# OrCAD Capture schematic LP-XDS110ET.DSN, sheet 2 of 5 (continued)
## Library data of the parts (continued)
R33 = RESISTOR: RESISTOR, THICK FILM, 51k, -5%/+5%, 0.063W, 50V, -55DEGC/+155DEGC, 0402, SMD; Additional Datasheet URL: N/A; AutoDoc File: https://notefied-dynamic-precision.com/DB/Apps/Desktop/Item/Object.aspx?id=114564; BU Name: TEXAS INSTRUMENTS NORWAY; Budget Currency: EUR; Budget Price: 0.014; Budgetary Price: 0.014 EUR; Client Status: UNDER_REVIEW; Country of Origin: Israel; Datasheet URL: http://www.vishay.com/docs/20035/dcrcwe3.pdf; Datasheet URL 1: http://www.vishay.com/docs/20035/dcrcwe3.pdf; Datasheet URL 2: N/A; Definied Quality: INDUSTRIAL; Esd Level: N/A; Exclusive for Customers: TEXAS INSTRUMENTS NORWAY; Lead Time: 18; LifeCycle Status: ACTIVE; MPN: RESISTOR_0402_51k_+/-5%_50V_0.063W_M_+/-200ppm; MPN Status: ACTIVE; MSL: N/A; MTBF: N/A; MTBF Standard: N/A; Manufacturer: MANUFACTURER SELECTION; Mass: 0.00065g; Max Oper Temp: +155DEGC; Max TC: +200PPM/DEGC; Max Tol: +5%; Maximum Operating Temperature: +155DEGC; Maximum Temperature Coefficient: +200PPM/DEGC; Maximum Tolerance: +5%; Min Oper Temp: -55DEGC; Min TC: -200PPM/DEGC; Min Tol: -5%; Minimum Operating Temperature: -55DEGC; Minimum Temperature Coeficient: -200PPM/DEGC; Minimum Tolerance: -5%; Mounting Type: SMD; NOTE Status: PREFERRED; NOTEfied URL: https://notefied-dynamic-precision.com/NOTEfiedWebInterface/part/show?partNumber=01-22491; Notes: Standard item: Duplicate Reason: custom footprint for TEXAS INSTRUMENTS NORWAY.; Old Footprint: RESC1005X40N; PCB Package: 0402; Packing Size: 10000; Packing Type: Tape & Reel; Part Number: 01-22491; Part Type: Resistor|0402|STANDARD; REACH/SVHC Compliance: Compliant; REACH/SVHC Details: SVHC List Version Jun 20, 2016; REACH/SVHC Source: Material Declaration; REACH/SVHC Status: Unaffected; REACH/SVHC_COMPLIANCE: COMPLIANT; REACH/SVHC_DETAILS: SVHC LIST VERSION Jun 20, 2016; REACH/SVHC_SOURCE: MATERIAL DECLARATION; REACH/SVHC_STATUS: UNAFFECTED; ROHS: Exempt; Rated Current: N/A; Rated Power: 0.063W; Rated Voltage: 50V; Resistor Type: THICK FILM; Revision: R007; RoHS Status: ROHS_COMPLIANT; Rtd Current: N/A; Rtd Power: 0.063W; Rtd Voltage: 50V; Status: Released; Texas Part Status: Under Review; Type: Resistor; Vendor: VISHAY; Vendor Part Number: CRCW040251K0JNED; Vendor Part Status: Active; WEIGHT: 0.00065g
R34 = RESISTOR: RESISTOR, THICK FILM, 30k, -5%/+5%, 0.063W, 50V, -55DEGC/+155DEGC, 0402, SMD; Additional Datasheet URL: N/A; AutoDoc File: https://notefied-dynamic-precision.com/DB/Apps/Desktop/Item/Object.aspx?id=114563; BU Name: TEXAS INSTRUMENTS NORWAY; Budget Currency: EUR; Budget Price: 0.014; Budgetary Price: 0.014 EUR; Client Status: UNDER_REVIEW; Country of Origin: Missing Info; Datasheet URL: http://www.vishay.com/docs/20035/dcrcwe3.pdf; Datasheet URL 1: http://www.vishay.com/docs/20035/dcrcwe3.pdf; Datasheet URL 2: N/A; Definied Quality: INDUSTRIAL; Esd Level: N/A; Exclusive for Customers: TEXAS INSTRUMENTS NORWAY; Lead Time: 18; LifeCycle Status: ACTIVE; MPN: RESISTOR_0402_30k_+/-5%_50V_0.063W_M_+/-200ppm; MPN Status: ACTIVE; MSL: N/A; MTBF: N/A; MTBF Standard: N/A; Manufacturer: MANUFACTURER SELECTION; Mass: 0.00065g; Max Oper Temp: +155DEGC; Max TC: +200PPM/DEGC; Max Tol: +5%; Maximum Operating Temperature: +155DEGC; Maximum Temperature Coefficient: +200PPM/DEGC; Maximum Tolerance: +5%; Min Oper Temp: -55DEGC; Min TC: -200PPM/DEGC; Min Tol: -5%; Minimum Operating Temperature: -55DEGC; Minimum Temperature Coeficient: -200PPM/DEGC; Minimum Tolerance: -5%; Mounting Type: SMD; NOTE Status: PREFERRED; NOTEfied URL: https://notefied-dynamic-precision.com/NOTEfiedWebInterface/part/show?partNumber=01-22490; Notes: Standard item: Duplicate Reason: custom footprint for TEXAS INSTRUMENTS NORWAY.; Old Footprint: RESC1005X40N; PCB Package: 0402; Packing Size: 10000; Packing Type: Tape & Reel; Part Number: 01-22490; Part Type: Resistor|0402|STANDARD; REACH/SVHC Compliance: Compliant; REACH/SVHC Details: SVHC List Version Jun 20, 2016; REACH/SVHC Source: Material Declaration; REACH/SVHC Status: Unaffected; REACH/SVHC_COMPLIANCE: COMPLIANT; REACH/SVHC_DETAILS: SVHC LIST VERSION Jun 20, 2016; REACH/SVHC_SOURCE: MATERIAL DECLARATION; REACH/SVHC_STATUS: UNAFFECTED; ROHS: Exempt; Rated Current: N/A; Rated Power: 0.063W; Rated Voltage: 50V; Resistor Type: THICK FILM; Revision: R007; RoHS Status: ROHS_COMPLIANT; Rtd Current: N/A; Rtd Power: 0.063W; Rtd Voltage: 50V; Status: Released; Texas Part Status: Under Review; Type: Resistor; Vendor: VISHAY; Vendor Part Number: CRCW040230K0JNED; Vendor Part Status: Active; WEIGHT: 0.00065g
R84 = RESISTOR: RESISTOR, THICK FILM, 12k, -1%/+1%, 0.05W, 30V, -55DEGC/+155DEGC, 0201, SMD; ALT_SYMBOLS: RESC0603X35B2L,RESC0603X35B2M; Additional Datasheet URL: N/A; AutoDoc File: https://notefied-dynamic-precision.com/DB/Apps/Desktop/Item/Object.aspx?id=58894; BU Name: DYNAMIC PRECISION GDANSK; Budget Currency: USD; Budget Price: 0.0195; Budgetary Price: 0.0195 USD; Country of Origin: Taiwan; Datasheet URL: http://www.vishay.com/docs/20052/crcw0201e3.pdf; Datasheet URL 1: http://www.vishay.com/docs/20052/crcw0201e3.pdf; Datasheet URL 2: N/A; Lead Time: 7; Mass: 0.00017g; Max Oper Temp: +155DEGC; Max TC: +100PPM/DEGC; Max Tol: +1%; Maximum Operating Temperature: +155DEGC; Maximum Temperature Coefficient: +100PPM/DEGC; Maximum Tolerance: +1%; Min Oper Temp: -55DEGC; Min TC: -100PPM/DEGC; Min Tol: -1%; Minimum Operating Temperature: -55DEGC; Minimum Temperature Coeficient: -100PPM/DEGC; Minimum Tolerance: -1%; Mounting Type: SMD; NOTEfied URL: https://notefied-dynamic-precision.com/NOTEfiedWebInterface/part/show?partNumber=01-04087; PCB Package: 0201; Packing Size: 10000; Packing Type: Tape & Reel; Part Number: 01-04087; Part Type: Resistor|0201|PRECISION; REACH/SVHC Compliance: Compliant; REACH/SVHC Details: SVHC List Version Jan 12, 2017; REACH/SVHC Source: REACH Declaration; REACH/SVHC Status: Unaffected; ROHS: Exempt; Rated Current: N/A; Rated Power: 0.05W; Rated Voltage: 30V; Resistor Type: THICK FILM; Revision: R007; RoHS Status: ROHS_COMPLIANT; Rtd Current: N/A; Rtd Power: 0.05W; Rtd Voltage: 30V; Status: Released; Texas Part Status: Under Review; Type: Resistor; Vendor: VISHAY; Vendor Part Number: CRCW020112K0FKED; Vendor Part Status: Active; Weight: 0.00017g
R87 = RESISTOR: RESISTOR, THICK FILM, 1M, -1%/+1%, 0.063W, 50V, -55DEGC/+155DEGC, 0402, SMD; Additional Datasheet URL: N/A; AutoDoc File: https://notefied-dynamic-precision.com/DB/Apps/Desktop/Item/Object.aspx?id=114549; BU Name: TEXAS INSTRUMENTS NORWAY; Budget Currency: EUR; Budget Price: 0.012; Budgetary Price: 0.012 EUR; Client Status: UNDER_REVIEW; Country of Origin: Israel; Datasheet URL: http://www.vishay.com/docs/20035/dcrcwe3.pdf; Datasheet URL 1: http://www.vishay.com/docs/20035/dcrcwe3.pdf; Datasheet URL 2: N/A; Exclusive for Customers: TEXAS INSTRUMENTS NORWAY; Lead Time: 14; Mass: 0.00060916g; Max Oper Temp: +155DEGC; Max TC: +100PPM/DEGC; Max Tol: +1%; Maximum Operating Temperature: +155DEGC; Maximum Temperature Coefficient: +100PPM/DEGC; Maximum Tolerance: +1%; Min Oper Temp: -55DEGC; Min TC: -100PPM/DEGC; Min Tol: -1%; Minimum Operating Temperature: -55DEGC; Minimum Temperature Coeficient: -100PPM/DEGC; Minimum Tolerance: -1%; Mounting Type: SMD; NOTEfied URL: https://notefied-dynamic-precision.com/NOTEfiedWebInterface/part/show?partNumber=01-22476; Notes: Standard item: Duplicate Reason: custom footprint for TEXAS INSTRUMENTS NORWAY.; PCB Package: 0402; Packing Size: 10000; Packing Type: Tape & Reel; Part Number: 01-22476; Part Type: Resistor|0402|PRECISION; REACH/SVHC Compliance: Compliant; REACH/SVHC Details: SVHC List Version Jun 20, 2016; REACH/SVHC Source: Material Declaration; REACH/SVHC Status: Unaffected; ROHS: Exempt; Rated Current: N/A; Rated Power: 0.063W; Rated Voltage: 50V; Resistance: 1M; Resistor Type: THICK FILM; Revision: R011; RoHS Status: ROHS_COMPLIANT_WITH_EXEMPTION; Rtd Current: N/A; Rtd Power: 0.063W; Rtd Voltage: 50V; Status: Released; Texas Part Status: Under Review; Type: Resistor; Vendor: VISHAY; Vendor Part Number: CRCW04021M00FKED; Vendor Part Status: Active; Weight: 0.00060916g
R93 = RESISTOR: RESISTOR, THICK FILM, 20k, -5%/+5%, 0.05W, 30V, -55DEGC/+155DEGC, 0201, SMD; ALT_SYMBOLS: RESC0603X35B2L,RESC0603X35B2M; Additional Datasheet URL: N/A; AutoDoc File: https://notefied-dynamic-precision.com/DB/Apps/Desktop/Item/Object.aspx?id=59010; BU Name: DYNAMIC PRECISION GDANSK; Budget Currency: USD; Budget Price: 0.0041; Budgetary Price: 0.0041 USD; Country of Origin: Taiwan; Datasheet URL: http://www.vishay.com/docs/20052/crcw0201e3.pdf; Datasheet URL 1: http://www.vishay.com/docs/20052/crcw0201e3.pdf; Datasheet URL 2: N/A; Lead Time: 7; Mass: 0.00017g; Max Oper Temp: +155DEGC; Max TC: +200PPM/DEGC; Max Tol: +5%; Maximum Operating Temperature: +155DEGC; Maximum Temperature Coefficient: +200PPM/DEGC; Maximum Tolerance: +5%; Min Oper Temp: -55DEGC; Min TC: -200PPM/DEGC; Min Tol: -5%; Minimum Operating Temperature: -55DEGC; Minimum Temperature Coeficient: -200PPM/DEGC; Minimum Tolerance: -5%; Mounting Type: SMD; NOTEfied URL: https://notefied-dynamic-precision.com/NOTEfiedWebInterface/part/show?partNumber=01-04203; PCB Package: 0201; Packing Size: 10000; Packing Type: Tape & Reel; Part Number: 01-04203; Part Type: Resistor|0201|STANDARD; REACH/SVHC Compliance: Compliant; REACH/SVHC Details: SVHC List Version Jan 12, 2017; REACH/SVHC Source: REACH Declaration; REACH/SVHC Status: Unaffected; ROHS: Exempt; Rated Current: N/A; Rated Power: 0.05W; Rated Voltage: 30V; Resistor Type: THICK FILM; Revision: R007; RoHS Status: ROHS_COMPLIANT; Rtd Current: N/A; Rtd Power: 0.05W; Rtd Voltage: 30V; Status: Released; Texas Part Status: Under Review; Type: Resistor; Vendor: VISHAY; Vendor Part Number: CRCW020120K0JNED; Vendor Part Status: Active; Weight: 0.00017g
R353 = RESISTOR: RESISTOR, THICK FILM, 4.7k, -5%/+5%, 0.063W, 50V, -55DEGC/+155DEGC, 0402, SMD; Additional Datasheet URL: N/A; Budgetary Price: 0.014 EUR; Country of Origin: Israel; Datasheet URL: http://www.vishay.com/docs/20035/dcrcwe3.pdf; Exclusive for Customers: TEXAS INSTRUMENTS NORWAY; Lead Time: 18; Mass: 0.00065g; Maximum Operating Temperature: +155DEGC; Maximum Temperature Coefficient: +200PPM/DEGC; Maximum Tolerance: +5%; Minimum Operating Temperature: -55DEGC; Minimum Temperature Coeficient: -200PPM/DEGC; Minimum Tolerance: -5%; Mounting Type: SMD; NOTEfied URL: https://notefied-dynamic-precision.com/NOTEfiedWebInterface/part/show?partNumber=01-22489; Notes: Standard item: Duplicate Reason: custom footprint for TEXAS INSTRUMENTS NORWAY.; PCB Package: 0402; Packing Size: 10000; Packing Type: Tape & Reel; Part Number: 01-22489; Part Type: Resistor|0402|STANDARD; REACH/SVHC Compliance: Compliant; REACH/SVHC Details: SVHC List Version Jun 20, 2016; REACH/SVHC Source: Material Declaration; REACH/SVHC Status: Unaffected; ROHS: Exempt; Rated Current: N/A; Rated Power: 0.063W; Rated Voltage: 50V; Resistor Type: THICK FILM; Revision: R009; Status: Released; Texas Part Status: Under Review; Type: Resistor; Vendor: VISHAY; Vendor Part Number: CRCW04024K70JNED; Vendor Part Status: Active
R357 R358 = RESISTOR: RESISTOR, THICK FILM, 5.1k, -5%/+5%, 0.05W, 30V, -55DEGC/+155DEGC, 0201, SMD; ALT_SYMBOLS: RESC0603X35B2L,RESC0603X35B2M; Additional Datasheet URL: N/A; Budgetary Price: 0.005 EUR; Country of Origin: Taiwan; Datasheet URL: https://www.vishay.com/docs/20052/crcw0201e3.pdf; Lead Time: 20; Mass: 0.00017g; Maximum Operating Temperature: +155DEGC; Maximum Temperature Coefficient: +200PPM/DEGC; Maximum Tolerance: +5%; Minimum Operating Temperature: -55DEGC; Minimum Temperature Coeficient: -200PPM/DEGC; Minimum Tolerance: -5%; Mounting Type: SMD; NOTEfied URL: https://notefied-dynamic-precision.com/NOTEfiedWebInterface/part/show?partNumber=01-04189; PCB Package: 0201; Packing Size: 10000; Packing Type: Tape & Reel; Part Number: 01-04189; Part Type: Resistor|0201|STANDARD; ROHS: Exempt; Rated Current: N/A; Rated Power: 0.05W; Rated Voltage: 30V; Resistor Type: THICK FILM; Revision: R008; Status: Released; Type: Resistor; Vendor: VISHAY; Vendor Part Number: CRCW02015K10JNED; Vendor Part Status: Active
U5 = IC_PROC_MSP432E401Y_TQFP128: IC, MICROCONTROLLER, SIMPLELINK ETHERNET MICROCONTROLLER, 2.97V TO 3.63V, TQFP128, SMD; ALT_SYMBOLS: QFP40P1600X1600X120-128A2L,QFP40P1600X1600X120-128A2M; Additional Datasheet URL: http://www.ti.com/lit/ml/mpqf013/mpqf013.pdf; Budgetary Price: 9.31 USD; Country of Origin: Philippines; Datasheet URL: http://www.ti.com/lit/ds/symlink/msp432e401y.pdf; Frequency: 120MHz; Mass: 0.5774g; Maximum Operating Temperature: +105DEGC; Minimum Operating Temperature: -40DEGC; Mounting Type: SMD; NOTEfied URL: https://notefied-dynamic-precision.com/NOTEfiedWebInterface/part/show?partNumber=18-35458; PCB Package: TQFP128; Packing Size: 90; Packing Type: Tray; Part Number: 18-35458; Part Type: IC|MICROCONTROLLER|TEXAS INSTRUMENTS; REACH/SVHC Compliance: Compliant; REACH/SVHC Details: SVHC List Version Jan 15, 2019; REACH/SVHC Source: REACH Declaration; REACH/SVHC Status: Unaffected; ROHS: Compliant; Rated Voltage: 2.97V TO 3.63V; Revision: R002; Status: Released; Texas Part Status: Under Review; Type: IC; Vendor: TEXAS INSTRUMENTS; Vendor Part Status: Active
U6 = IC_REF_LM4040_SC70-5: IC, ANALOG, PRECISION MICROPOWER SHUNT VOLTAGE REFERENCE, 2.5V, SC70-5, SMD; ALT_SYMBOLS: SOT65P210X110-5L,SOT65P210X110-5M; Additional Datasheet URL: http://www.ti.com/litv/pdf/mpds025f; AutoDoc File: http://notefied-dynamic-precision.com/DB/Apps/Desktop/Item/Object.aspx?id=96645; Budget Currency: USD; Budget Price: 0.78; Budgetary Price: 0.71 USD; Country of Origin: Missing Info; Datasheet URL: http://www.ti.com/lit/ds/symlink/lm4040.pdf; Datasheet URL 1: http://www.ti.com/lit/ml/mpds025f/mpds025f.pdf; Datasheet URL 2: http://www.ti.com/lit/ds/symlink/lm4040b25.pdf; Definied Quality: INDUSTRIAL; Esd Level: N/A; FPLIST: SOT65P210X110-5N,SOT65P210X110-5L,SOT65P210X110-5M; Lead Time: 7; MPN: LM4040B25IDCKR; MPN Status: ACTIVE; MSL: 1; Manufacturer: TEXAS INSTRUMENTS; Mass: 0.0068g; Max Oper Temp: +85DEGC; Maximum Operating Temperature: +85DEGC; Min Oper Temp: -40DEGC; Minimum Operating Temperature: -40DEGC; Mounting Type: SMD; NOTE Status: PREFERRED; NOTEfied URL: https://notefied-dynamic-precision.com/NOTEfiedWebInterface/part/show?partNumber=18-29558; PCB Package: SC70-5; Packing Size: 3000; Packing Type: Tape & Reel; Part Number: 18-29558; Part Type: IC|ANALOG|PM|REFERENCE; REACH/SVHC Compliance: Compliant; REACH/SVHC Details: SVHC List Version Jun 20, 2016; REACH/SVHC Source: Material Declaration; REACH/SVHC Status: Unaffected; ROHS: Compliant; Rated Voltage: 2.5V; Revision: R006; RoHS Status: ROHS_COMPLIANT; Rtd Voltage: 2.5V; Status: Released; Texas Part Status: Under Review; Type: IC; Vendor: TEXAS INSTRUMENTS; Vendor Part Number: LM4040B25IDCKR; Vendor Part Status: Active; WEIGHT: 0.011098173g
U7 = IC_PM_TPS79601_SON8: IC, ANALOG, ULTRALOW-NOISE, HIGH PSRR, FAST, RF, 1A LOW-DROPOUT LINEAR REGULATORS, VIN:2.7V TO 5.5V, VOUT:1.2V TO 5.5V, SON8, SMD; ALT_SYMBOLS: SON65P300X300X100-9AL,SON65P300X300X100-9AM; Additional Datasheet URL: http://www.ti.com/litv/pdf/mpds118j; AutoDoc File: http://notefied-dynamic-precision.com/DB/Apps/Desktop/Item/Object.aspx?id=96546; Budget Currency: USD; Budget Price: 1; Budgetary Price: 1 USD; Country of Origin: Malaysia; Datasheet URL: http://www.ti.com/lit/ds/symlink/tps796.pdf; Datasheet URL 1: http://www.ti.com/litv/pdf/mpds118j; Datasheet URL 2: http://www.ti.com/lit/ds/symlink/tps79601.pdf; FPLIST: SON65P300X300X100-9AN,SON65P300X300X100-9AL,SON65P300X300X100-9AM; Lead Time: 6; LifeCycle Status: ACTIVE; MPN: TPS79601DRBR; MPN Status: ACTIVE; MSL: 2; Manufacturer: TEXAS INSTRUMENTS; Mass: 0.0247g; Max Oper Temp: +125DEGC; Maximum Operating Temperature: +125DEGC; Min Oper Temp: -40DEGC; Minimum Operating Temperature: -40DEGC; Mounting Type: SMD; NOTE Status: PREFERRED; NOTEfied URL: https://notefied-dynamic-precision.com/NOTEfiedWebInterface/part/show?partNumber=18-29530; PCB Package: SON8; Packing Size: 3000; Packing Type: Tape & Reel; Part Number: 18-29530; Part Type: IC|ANALOG|PM|REGULATOR; REACH/SVHC Compliance: Compliant; REACH/SVHC Details: SVHC List Version Jun 20, 2016; REACH/SVHC Source: Material Declaration; REACH/SVHC Status: Unaffected; ROHS: Compliant; Rated Voltage: 1.2V TO 5.4V; Revision: R006; RoHS Status: ROHS_COMPLIANT; Rtd Voltage: 1.2V TO 5.4V; Status: Released; Texas Part Status: Under Review; Type: IC; Vendor: TEXAS INSTRUMENTS; Vendor Part Number: TPS79601DRBR; Vendor Part Status: Active; WEIGHT: 0.024660813g
U15 = IC_PROC_USB3300_QFN32: IC, DIGITAL, INTERFACE, HI-SPEED USB HOST, 3.3V, QFN32-EP, SMD; ALT_SYMBOLS: QFNWB50P500X500X100-33L,QFNWB50P500X500X100-33M,QFNWB50P500X500X100-33DL,QFNWB50P500X500X100-33DM; Additional Datasheet URL: http://www.microchip.com/wwwproducts/Devices.aspx?product=USB3300#pricindAndSamples; AutoDoc File: https://notefied-dynamic-precision.com/DB/Apps/Desktop/Item/Object.aspx?id=73764; BU Name: DYNAMIC PRECISION GDANSK; Budget Currency: USD; Budget Price: 0.91; Budgetary Price: 0.91 USD; CLASS: IC; Client Status: UNDER_REVIEW; Country of Origin: China; Datasheet URL: http://ww1.microchip.com/downloads/en/DeviceDoc/00001783C.pdf; Datasheet URL 1: http://ww1.microchip.com/downloads/en/DeviceDoc/00001783B.pdf; Datasheet URL 2: http://www.microchip.com/wwwproducts/Devices.aspx?product=USB3300#pricindAndSamples; FPLIST: QFNWB50P500X500X100-33N,QFNWB50P500X500X100-33DN; Lead Time: 2; Mass: 0.0636g; Max Oper Temp: +85DEGC; Maximum Operating Temperature: +85DEGC; Min Oper Temp: -40DEGC; Minimum Operating Temperature: -40DEGC; Mounting Type: SMD; NOTEfied URL: https://notefied-dynamic-precision.com/NOTEfiedWebInterface/part/show?partNumber=18-26311; PCB Package: QFN32-EP; Packing Size: 4900; Packing Type: Tray; Part Number: 18-26311; Part Type: IC|DIGITAL|INTERFACE|USB; REACH/SVHC Compliance: Compliant; REACH/SVHC Details: SVHC List Version Jun 20, 2016; REACH/SVHC Source: Material Declaration; REACH/SVHC Status: Unaffected; ROHS: Compliant; Rated Voltage: 3.3V; Revision: R010; RoHS Status: ROHS_COMPLIANT; Rtd Voltage: 3.3V; Status: Released; Texas Part Status: Under Review; Type: IC; Vendor: MICROCHIP; Vendor Part Status: Active; Weight: 0.0636g
U47 = IC_PM_TPS259530_WSON8: IC, ANALOG, EFUSE WITH FAST OVERVOLTAGE PROTECTION, 2.7V TO 18V, WSON8-EP, SMD; ALT_SYMBOLS: SON50P200X200X80-9A2L,SON50P200X200X80-9A2M; Additional Datasheet URL: N/A; Budgetary Price: 0.4 USD; Datasheet URL: http://www.ti.com/lit/ds/symlink/tps2595.pdf; Mass: 0.0119g; Maximum Operating Temperature: +125DEGC; Minimum Operating Temperature: -40DEGC; Mounting Type: SMD; NOTEfied URL: https://notefied-dynamic-precision.com/NOTEfiedWebInterface/part/show?partNumber=18-34886; PCB Package: WSON8-EP; Packing Size: 3000; Packing Type: Tape & Reel; Part Number: 18-34886; Part Type: IC|ANALOG|PM|HOTSWAP; REACH/SVHC Details: SVHC List Version; ROHS: Compliant; Rated Current: 4A; Rated Voltage: 2.7V TO 18V; Revision: R001; Status: Released; Texas Part Status: Under Review; Type: IC; Vendor: TEXAS INSTRUMENTS; Vendor Part Number: TPS259530DSGR; Vendor Part Status: Active
Y3 = XTAL_4: CRYSTAL, RESONATOR, 16MHz, -30PPM/+30PPM, -40DEGC/+85DEGC, SMD; ALT_SYMBOLS: OSCCC250X320X100-4BL,OSCCC250X320X100-4BM; Additional Datasheet URL: http://www.ndk.com/en/products/search/crystal/1188120_1494.html; AutoDoc File: http://notefied-dynamic-precision.com/DB/Apps/Desktop/Item/Object.aspx?id=96470; Budgetary Price: 0.3881 USD; Capacitance: 8pF; Country of Origin: Missing Info; Datasheet URL: http://www.ndk.com/images/products/catalog/c_NX3225GA-STD-CRG-2_e.pdf; Datasheet URL 1: N/A; Datasheet URL 2: http://www.ndk.com/images/products/catalog/c_NX3225GA-STD-CRG-2_e.pdf; FPLIST: OSCCC250X320X100-4BN,OSCCC250X320X100-4BL,OSCCC250X320X100-4BM; MPN: NX3225GA-16.000M-STD-CRG-1; MPN Status: ACTIVE; Manufacturer: NIHON DEMPA KOGYO; Mass: N/A; Max Oper Temp: +85DEGC; Max TC: +30PPM/DEGC; Max Tol: +20PPM; Maximum Operating Temperature: +85DEGC; Maximum Stability: +30PPM; Maximum Tolerance: +20PPM; Min Oper Temp: -40DEGC; Min TC: -30PPM/DEGC; Min Tol: -20PPM; Minimum Operating Temperature: -40DEGC; Minimum Stability: -30PPM; Minimum Tolerance: -20PPM; Mounting Type: SMD; NOTE Status: PREFERRED; NOTEfied URL: https://notefied-dynamic-precision.com/NOTEfiedWebInterface/part/show?partNumber=12-00745; Packing Size: 3000; Packing Type: Tape & Reel; Part Number: 12-00745; Part Type: Crystal|RESONATOR; REACH/SVHC Compliance: Compliant; REACH/SVHC Details: SVHC List Version Jun 20, 2016; REACH/SVHC Source: REACH Declaration; REACH/SVHC Status: Unaffected; ROHS: Exempt; Rated Voltage: N/A; Revision: R009; RoHS Status: ROHS_COMPLIANT; Status: Released; Texas Part Status: Under Review; Type: Crystal; Vendor: NIHON DEMPA KOGYO; Vendor Part Number: NX3225GA-16.000M-STD-CRG-1; Vendor Part Status: Active
Y4 = XTAL_4: CRYSTAL, RESONATOR, 24MHz, -50PPM/+50PPM, -40DEGC/+85DEGC, SMD; ALT_SYMBOLS: OSCCC250X320X70-4AL,OSCCC250X320X70-4AM; Additional Datasheet URL: http://www5.epsondevice.com/en/products/crystal_unit/fa238.html; AutoDoc File: https://notefied-dynamic-precision.com/DB/Apps/Desktop/Item/Object.aspx?id=96049; BU Name: DYNAMIC PRECISION GDANSK; Budget Currency: N/A; Budget Price: N/A; Capacitance: 12pF; Client Status: UNDER_REVIEW; Country of Origin: Japan; Datasheet URL: https://support.epson.biz/td/api/doc_check.php?mode=dl&lang=en&Parts=FA-238; Datasheet URL 1: https://support.epson.biz/td/api/doc_check.php?mode=dl&lang=en&Parts=FA-238; Datasheet URL 2: http://www5.epsondevice.com/en/products/mhz_range/fa238.html; Mass: 0.016g; Max Oper Temp: +85DEGC; Max TC: +50PPM; Max Tol: +50PPM; Maximum Operating Temperature: +85DEGC; Maximum Stability: +50PPM; Maximum Tolerance: +50PPM; Min Oper Temp: -40DEGC; Min TC: -50PPM; Min Tol: -50PPM; Minimum Operating Temperature: -40DEGC; Minimum Stability: -50PPM; Minimum Tolerance: -50PPM; Mounting Type: SMD; NOTEfied URL: https://notefied-dynamic-precision.com/NOTEfiedWebInterface/part/show?partNumber=12-00730; Packing Size: 1000; Packing Type: Tape & Reel; Part Number: 12-00730; Part Type: Crystal|RESONATOR; REACH/SVHC Compliance: Compliant; REACH/SVHC Details: SVHC List Version Jan 12, 2017; REACH/SVHC Source: REACH Declaration; REACH/SVHC Status: Unaffected; ROHS: Compliant; Rated Voltage: N/A; Revision: R008; RoHS Status: ROHS_COMPLIANT; Rtd Voltage: N/A; Status: Released; Texas Part Status: Under Review; Type: Crystal; Vendor: EPSON; Vendor Part Number: FA-238 24.0000MB50X-W0; Vendor Part Status: Active; Weight: 0.016g

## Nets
5V0: C48.1 C110.1 C111.1 FL2.1 R92.2 U7.1(IN) U7.2(IN) U7.8(EN) ; also on sheet 1 4
GND: C1.2 C2.2 C3.2 C4.2 C6.2 C7.2 C8.2 C9.2 C38.2 C39.2 C40.2 C42.2 C43.2 C44.2 C45.2 C46.2 C48.2 C49.2 C50.2 C78.2 C79.2 C80.2 C83.2 C84.2 C85.2 C86.2 C87.2 C88.1 C89.2 C108.2 C109.2 C110.2 C111.2 C113.2 CR4.1(C) CR5.1(C) CR6.3 CR15.2(ANODE) J1.C1(GND) J1.C2(GND) J1.C15(GND) J1.C16(GND) J1.M1(SHIELD) J1.M2(SHIELD) J1.M3(SHIELD) J1.M4(SHIELD) P8.3(7) P8.5(8) P8.9(10) R28.1 R29.2 R30.2 R34.1 R84.1 R90.1 R91.1 R93.2 R353.1 R357.1 R358.1 U5.10(GNDA) U5.17(GND) U5.48(GND) U5.55(GND) U5.58(GND) U5.64(nWAKE) U5.66(XOSC0) U5.80(GND) U5.114(GND) U6.1(ANODE) U7.6(GND) U7.9(GND/TAB) U15.1(GND) U15.2(GND) U15.33(EGP) U47.8(GND) U47.9(EGP) Y3.2 Y3.4 Y4.2 Y4.4 ; also on sheet 1 3 4 5
VBUS_DET: R92.1 R93.1 U5.12(PE3/AIN0)
VDDC: C43.1 C44.1 C45.1 U5.87(VDDC) U5.115(VDDC)
ET_BYPASS: U5.78(PM0) ; also on sheet 3
ET_CAL0: U5.74(PM4) ; also on sheet 3
ET_CAL1: U5.73(PM5) ; also on sheet 3
ET_CAL2: U5.23(PC6/C0+) ; also on sheet 3
ET_CALIBRATE: U5.77(PM1) ; also on sheet 3
ET_PM2: U5.76(PM2) ; also on sheet 3
ET_PN3: U5.110(PN3) ; also on sheet 3
ET_SSICLK: U5.120(PB5/AIN11) ; also on sheet 3
ET_SSIDAT0: U5.123(PE4/AIN9) ; also on sheet 3
ET_SSIDAT1: U5.124(PE5/AIN8) ; also on sheet 3
ET_SSIFSS: U5.121(PB4/AIN10) ; also on sheet 3
IRSTn: P8.10(5) R20.2
ITCK: P8.4(2) U5.100(PC0/TCK/SWCLK)
ITDI: P8.8(4) U5.98(PC2/TDI)
ITDO: P8.6(3) U5.97(PC3/TDO/SWO)
ITMS: P8.2(1) U5.99(PC1/TMS/SWDIO)
USB1V8: C83.1 C84.1 C85.1 U15.15(VDD1.8) U15.26(VDD1.8)
USB_VBUS: CR6.6 J1.C3(VBUS) J1.C4(VBUS) J1.C13(VBUS) J1.C14(VBUS) R82.2 U47.2(EN/UVLO) U47.3(IN) U47.4(IN)
USBA1V8: C86.1 C87.1 U15.29(VDDA1.8)
USBCLK: U5.92(PB3/I2C0SDA) U15.14(CLKOUT)
USBD0: U5.81(PL0) U15.24(DATA0)
USBD1: U5.82(PL1) U15.23(DATA1)
USBD2: U5.83(PL2) U15.22(DATA2)
USBD3: U5.84(PL3) U15.21(DATA3)
USBD4: U5.85(PL4) U15.20(DATA4)
USBD5: U5.86(PL5) U15.19(DATA5)
USBD6: U5.106(PP5) U15.18(DATA6)
USBD7: U5.105(PP4) U15.17(DATA7)
USBDIR: U5.104(PP3) U15.12(DIR)
USBDM: CR6.4 J1.C7(DN1) J1.C10(DN2) U15.8(DM)
USBDP: CR6.5 J1.C6(DP1) J1.C11(DP2) U15.7(DP)
USBNXT: U5.103(PP2) U15.11(NXT)
USBSTP: U5.91(PB2/I2C0SCL) U15.13(STP)
XDS_BID_SCL: U5.112(PN5) ; also on sheet 1
XDS_BID_SDA: U5.111(PN4) ; also on sheet 1
XDS_DIR_GPIO1: U5.116(PJ0) ; also on sheet 1
XDS_DIR_GPIO2: U5.117(PJ1) ; also on sheet 1
XDS_GPIO1: U5.43(PF1) ; also on sheet 1
XDS_GPIO2: U5.44(PF2) ; also on sheet 1
XDS_GPIO3: U5.42(PF0) ; also on sheet 1
XDS_nCS: U5.6(PQ1) ; also on sheet 1
XDS_PICO: U5.11(PQ2) ; also on sheet 1
XDS_POCI: U5.27(PQ3) ; also on sheet 1
XDS_RESET: U5.40(PA6) ; also on sheet 1
XDS_RX: U5.33(PA0/U0RX) ; also on sheet 1
XDS_SCLK: U5.5(PQ0) ; also on sheet 1
XDS_SWO: U5.25(PC4/C1-) ; also on sheet 1
XDS_TCK: U5.35(PA2/SSI0CLK) ; also on sheet 1
XDS_TDI: U5.38(PA5/SSI0XDAT1) ; also on sheet 1
XDS_TDO: U5.37(PA4/SSI0XDAT0) ; also on sheet 1
XDS_TMS: U5.36(PA3/SSI0FSS) ; also on sheet 1
XDS_TMS_DIR: U5.24(PC5/C1+) ; also on sheet 1
XDS_TX: U5.34(PA1/U0TX) ; also on sheet 1
XDS_VDD: C2.1 C3.1 C4.1 C6.1 C7.1 C38.1 C39.1 C40.1 C42.1 C47.1 C49.1 C78.1 C79.1 C80.1 C113.1 P8.1(6) R17.2 R18.2 R27.1 R31.2 R33.2 R39.1 R83.1 U5.7(VDD) U5.8(VDDA) U5.16(VDD) U5.26(VDD) U5.28(VDD) U5.39(VDD) U5.47(VDD) U5.51(VDD) U5.52(VDD) U5.69(VDD) U5.79(VDD) U5.90(VDD) U5.101(VDD) U5.113(VDD) U5.122(VDD) U7.3(OUT) U7.4(OUT) U15.6(VDD3.3) U15.16(VDD3.3) U15.25(VDD3.3) U15.30(VDD3.3) U15.31(REG_EN) ; also on sheet 1
N2941019: R90.2 U5.95(PB0/USB0ID)
N2941087: R91.2 U5.96(PB1/USB0VBUS)
N2941323: R25.2 U5.4(PD3/AIN12)
N2941987: C89.1 R87.2 U15.28(XI) Y4.1
N2942075: C88.2 R87.1 U15.27(XO) Y4.3
N2942253: R83.2 U15.5(ID)
N2942419: R39.2 U5.63(PK4)
N2942527: R84.2 U15.32(RBIAS)
N2942551: R27.2 U5.62(PK5)
N2942639: R29.1 U5.61(PK6)
N2942779: R30.1 U5.60(PK7)
N2943199: C46.1 R31.1 U5.68(VBAT)
N2943999: R17.1 R20.1 U5.70(nRST)
N2944041: C8.1 C50.1 R18.1 U5.9(VREFA+) U6.3(CATHODE)
N2944467: C47.2 R33.1 R34.2 U7.5(FB)
N2944509: C9.1 U5.88(OSC0) Y3.1
N2944561: C1.1 U5.89(OSC1) Y3.3
N2944733: R28.2 U5.59(RBIAS)
N3010981: C109.1 CR15.1(CATHODE) FL2.2 U47.5(OUT)
N3012487: C108.1 U47.1(DVDT)
N3014332: R353.2 U47.7(ILIM)
N3192940: R23.2 U5.3(PD2/AIN13)
N3361245: CR4.2(A) R23.1
N3361246: R82.1 U15.4(VBUS)
N3361248: CR5.2(A) R25.1
N3400495: J1.C5(CC1) R357.2
N3400502: J1.C12(CC2) R358.2

Not connected (* = marked no-connect by the designer): CR6 1* 2*; J1 C8(SBU1) C9(SBU2); P8 7(9)*; U5 1(PD0/AIN15)* 2(PD1/AIN14)* 13(PE2/AIN1)* 14(PE1/AIN2)* 15(PE0/AIN3)* 18(PK0/AIN16)* 19(PK1/AIN17)* 20(PK2/AIN18)* 21(PK3/AIN19)* 22(PC7/C0-)* 29(PH0)* 30(PH1)* 31(PH2)* 32(PH3)* 41(PA7)* 45(PF3)* 46(PF4)* 49(PG0)* 50(PG1)* 53(EN0RXIN)* 54(EN0RXIP)* 56(EN0TXON)* 57(EN0TXOP)* 65(nHIB)* 67(XOSC1)* 71(PM7)* 72(PM6)* 75(PM3)* 93(PL7/USB0DM)* 94(PL6/USB0DP)* 102(PQ4)* 107(PN0)* 108(PN1)* 109(PN2)* 118(PP0/C2+)* 119(PP1/C2-)* 125(PD4/AIN7)* 126(PD5/AIN6)* 127(PD6/AIN5)* 128(PD7/AIN4)*; U6 2(NC)* 4(NC)* 5(NC)*; U7 7(NC)*; U15 3(CPEN)* 9(RESET)* 10(EXTVBUS)*; U47 6(nFLT)*

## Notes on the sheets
sheet 2
- XDS110 Debugger
- Pin 69
- Pin 51
- GREEN
- RED
- Pin 28
- Pin 113
- Pin 101
- XDS_VDD = 3.3 V
